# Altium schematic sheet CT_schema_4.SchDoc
size 314 x 312 mm
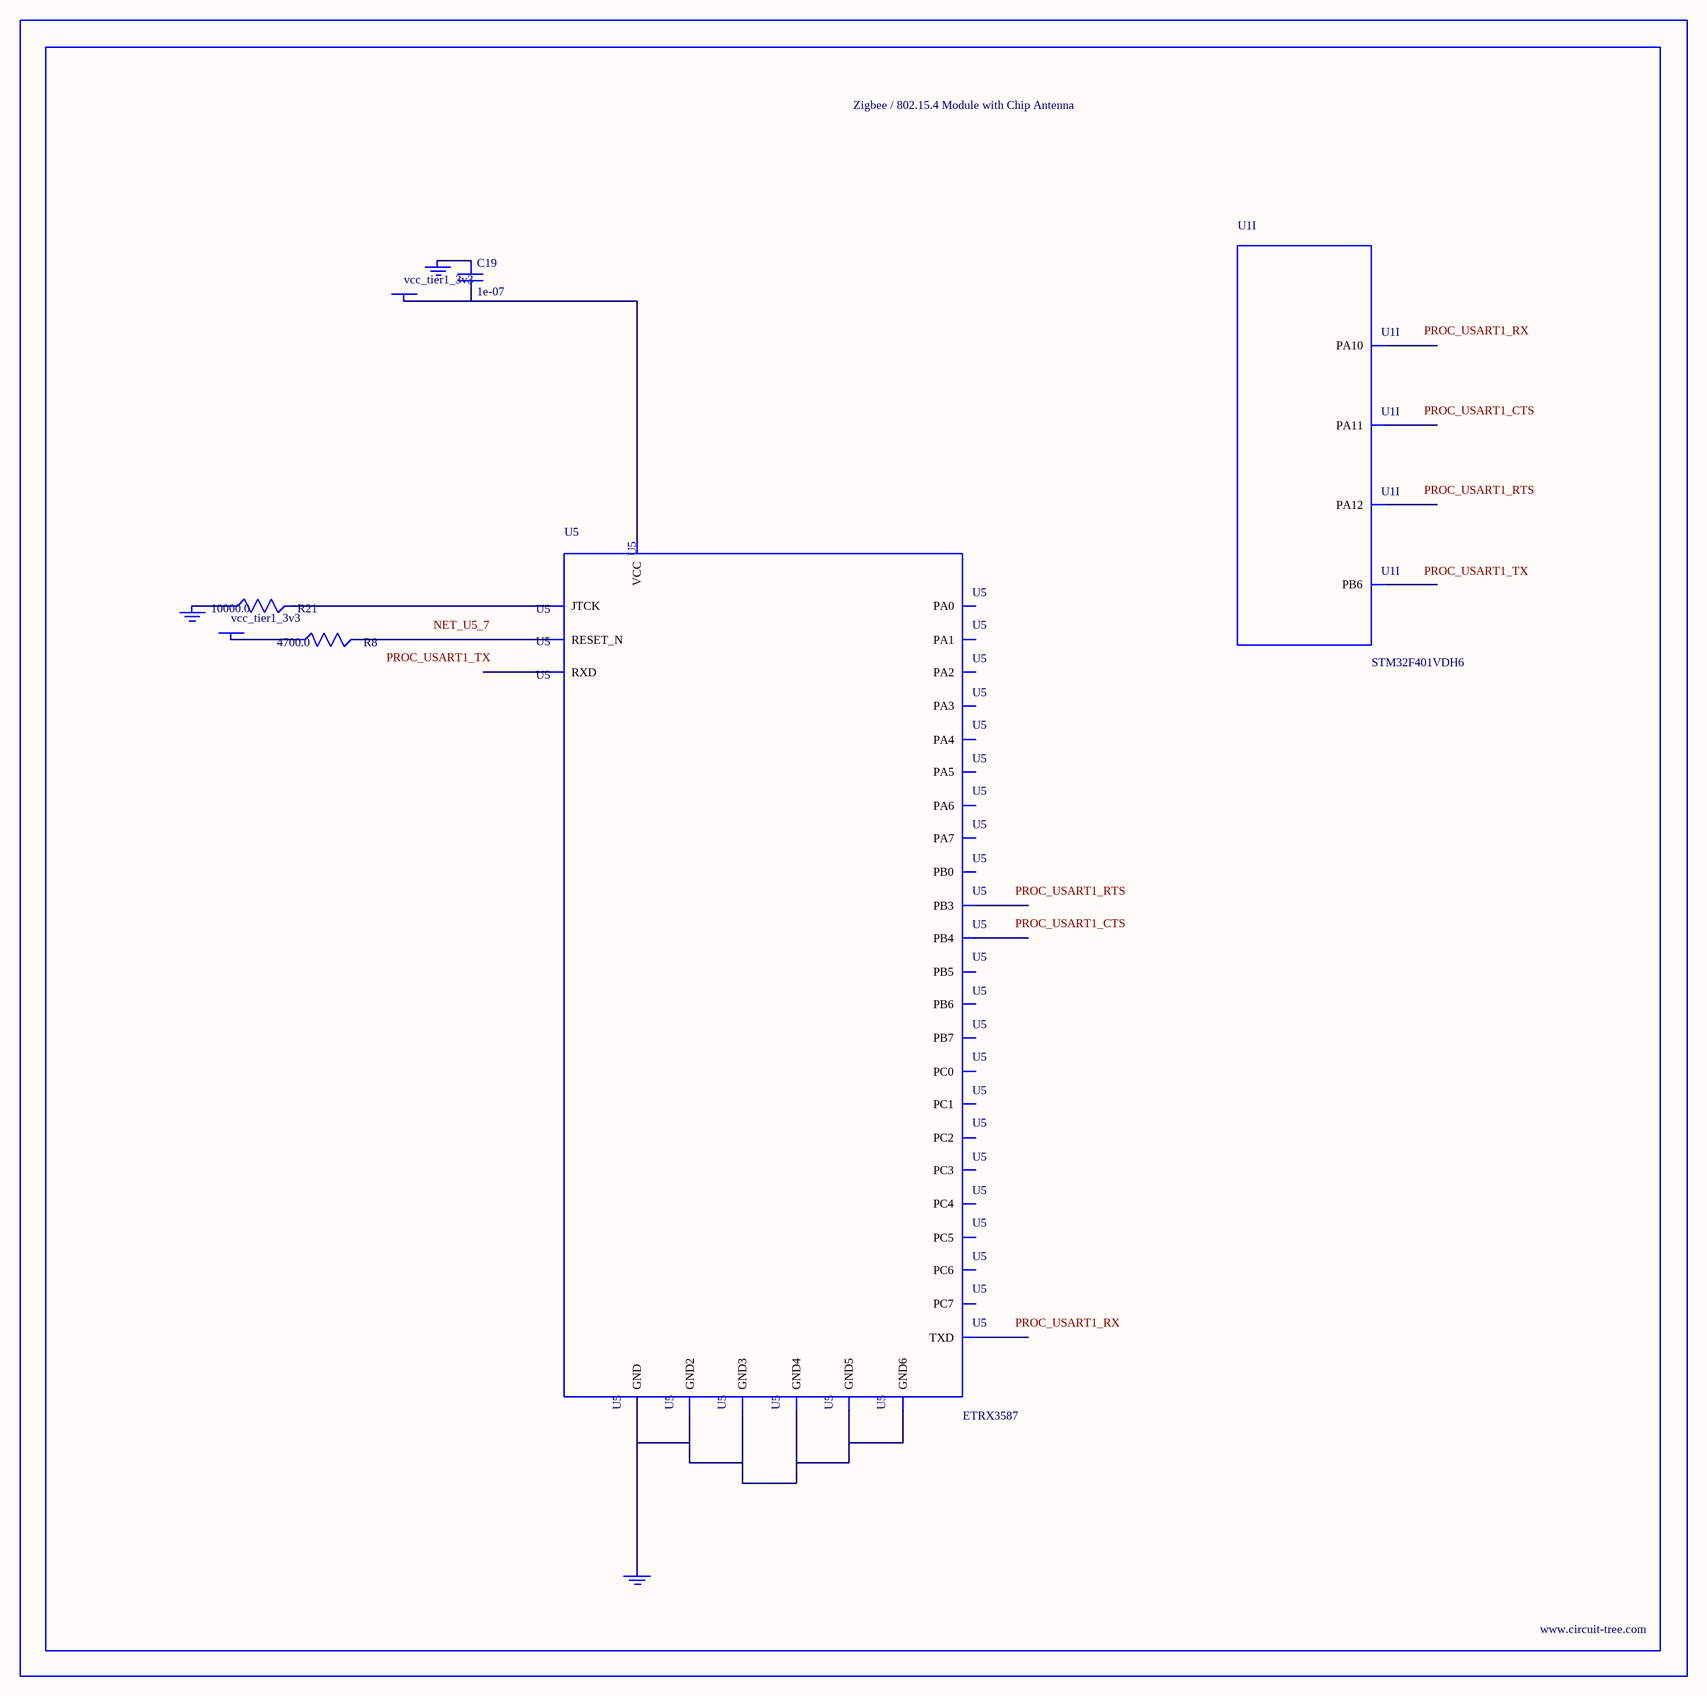
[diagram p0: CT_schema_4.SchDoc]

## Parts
BORDER3  (no value)
C19  1e-07  [C0402]
GND_INSTANCE_3_0  (no value)
GND_INSTANCE_3_1  (no value)
GND_INSTANCE_3_2  (no value)
POWER_INSTANCE_3_0  vcc_tier1_3v3
POWER_INSTANCE_3_1  vcc_tier1_3v3
R8  4700.0  [R0603]
R21  10000.0  [R0603]
U1  STM32F401VDH6  [UFBGA100]  (part I of 10)
U5  ETRX3587  [ETRX3587]

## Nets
NetC19_1: C19.1 GND_INSTANCE_3_1.0(GND)
NetC19_2: C19.2 POWER_INSTANCE_3_0.0(PWR) U5.32(VCC)
NetGND_INSTANCE_3_0_0: GND_INSTANCE_3_0.0(GND) R21.1
NetGND_INSTANCE_3_2_0: GND_INSTANCE_3_2.0(GND) U5.1(GND) U5.13(GND2) U5.19(GND3) U5.20(GND4) U5.31(GND5) U5.33(GND6)
NetPOWER_INSTANCE_3_1_0: POWER_INSTANCE_3_1.0(PWR) R8.1
NetR8_2: R8.2 U5.7(RESET_N)
NetR21_2: R21.2 U5.21(JTCK)

Not connected (* = marked no-connect by the designer): U1 A12(PA12) B5(PB6) B12(PA11) C12(PA10); U5 2(PC5) 3(PC6) 4(PC7) 5(PA7) 6(PB3) 8(PB4) 9(PA0) 10(PA1) 11(PA2) 12(PA3) 14(PA4) 15(PA5) 16(PA6) 17(TXD) 18(RXD) 22(PC2) 23(PC3) 24(PC4) 25(PB0) 26(PC1) 27(PC0) 28(PB7) 29(PB6) 30(PB5)

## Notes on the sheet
- Labels drawn without touching a wire or pin: NET_U5_7, PROC_USART1_CTS, PROC_USART1_RTS, PROC_USART1_RX, PROC_USART1_TX

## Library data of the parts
BORDER3 = BORDER_PAGE3
C19 = C0402C104K3RACTU
GND_INSTANCE_3_0-GND_INSTANCE_3_2 = GND
POWER_INSTANCE_3_0 POWER_INSTANCE_3_1 = PWR
R8 = RC0603JR-074K7L
R21 = RC0603JR-0710KL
